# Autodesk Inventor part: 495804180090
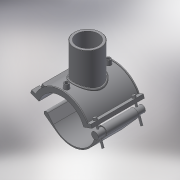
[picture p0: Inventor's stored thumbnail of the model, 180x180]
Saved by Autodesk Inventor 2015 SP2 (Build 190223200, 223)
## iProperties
Created: 2017-07
Part Number: 495804180090
Material: Generic
Description: PLASSON BRANCH SADDLE 180-90
Document SubType Name: Modeling
Designer: KIM
Density: 1 g/cm^3
Appearance: Default
Author: KIM
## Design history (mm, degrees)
derived "495804.ipt"
feature "Solid1::495804.ipt"
feature "Solid2::495804.ipt"
tag "TaggingFeature1"
body "Solid1"
body "Solid2"
other parameters: "d2" = 236.6, "d3" = 45, "d4" = 176, "d5" = 0, "d6" = 0.1, "d8" = 0, "d19" = 6, "d20" = 6, "d21" = 105.6, "d23" = 0, "d24" = 52.8, "d26" = 0, "d27" = 3, "d28" = 3, "d29" = 3, "d31" = 6, "d32" = 0, "d33" = 0, "d34" = 0.6, "d40" = 109.2, "d41" = 99, "d43" = 0, "d45" = 0, "d50" = 0, "d70" = 15, "d72" = 0, "d73" = 6, "d75" = 5, "d76" = 0, "d77" = 9, "d79" = 15, "d80" = 70.4, "d82" = 5 deg, "d84" = 4, "d85" = 14, "d86" = 0, "d87" = 3, "d88" = 0, "d89" = 1, "d90" = 1, "d91" = 140.8, "d92" = 0, "d93" = 0.5, "d94" = 94.73684, "d96" = 214.2, "d97" = 3.52, "d98" = 0, "d102" = 2.7, "d103" = 72, "d105" = 0, "d109" = -35, "d117" = 0.9, "d120" = 140 deg, "d121" = 24.228, "d122" = 20 deg, "d124" = 126, "d126" = 0, "d143" = 189, "d150" = 32.4, "d159" = 6, "d161" = 4.5, "d162" = 105.6, "d163" = 0, "d167" = 36, "d168" = 95.45455, "d173" = 1, "d176" = 20 deg, "d177" = 12.6, "d180" = 0, "d185" = 57.2, "d186" = 57.2, "d187" = 105, "d188" = 9, "d189" = 12.6, "d190" = 0, "d191" = 157.5, "d200" = 15, "d202" = 0, "d216" = 158.4, "d217" = 0, "d221" = 65.12, "d222" = 12.6, "d223" = 7.56, "d225" = 7.56, "d227" = 25.92, "d230" = 113.4, "d236" = 20 deg, "d237" = 112, "d238" = 20 deg, "d239" = 12.6, "B_" = 182, "H_" = 105, "L_" = 176, "d_t" = 6, "d148" = 4.5, "d160" = 4.5
